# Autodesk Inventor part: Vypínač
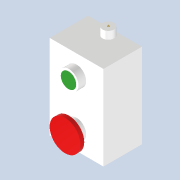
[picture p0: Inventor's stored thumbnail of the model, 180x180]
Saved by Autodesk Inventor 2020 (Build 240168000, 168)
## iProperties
Created: 2025-03
Part Number: Vypínač
Material: PC/ABS plast
Document SubType Name: Modeling
Designer: doma
Density: 0.357273 g/cm^3
Appearance: Hladká – bílá
Author: doma
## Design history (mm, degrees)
sketch "Náčrt1"
  geometry: L1 (-35, -55)-(35, -55); L2 (35, -55)-(35, 55); L3 (35, 55)-(-35, 55); L4 (-35, 55)-(-35, -55); L5 (-35, -55)-(35, 55); L6 (35, -55)-(-35, 55); 1 further point
  constraints: 12 end point, 2 midpoint, 2 parallel, 1 horizontal, 1 perpendicular
  dimensions: "d0" = 70 distance of L3.end L2.end; "d1" = 110 distance of L2.end L1.end
extrude "Vysunutí1" new body sketch "Náčrt1" distance "d2" = 50; taper "d3" = 0 deg
feature "Skořepina1" dims "d4" = 5
sketch "Náčrt2"
  geometry: C1 r 12.5 at (0, 30); C2 r 10 at (0, 30); 1 further point
  constraints: 2 centre point, 1 coincident
  dimensions: "d5" = 25 diameter of C1; "d6" = 20 diameter of C2; "d17" = 30 distance of C1.centre point (0, 0)
extrude "Vysunutí2" join sketch "Náčrt2" distance "d7" = 10; taper "d8" = 0 deg
extrude "Vysunutí3" join sketch "Náčrt2" distance "d9" = 10.5; taper "d10" = 0 deg
sketch "Náčrt3"
  geometry: C1 r 12.5 at (0, -30); 1 further point
  constraints: 1 centre point
  dimensions: "d11" = 25 diameter of C1; "d18" = 30 distance of C1.centre point (0, 0)
extrude "Vysunutí4" join sketch "Náčrt3" distance "d12" = 10; taper "d13" = 0 deg
sketch "Náčrt4"
  geometry: C1 r 12.5 at (0, 0) reference; C2 r 20 at (0, 0); 1 further point
  constraints: 1 centre point, 1 coincident
  dimensions: "d14" = 40 diameter of C2
extrude "Vysunutí5" join sketch "Náčrt4" distance "d15" = 5; taper "d16" = 0 deg
sketch "Náčrt5"
  geometry: C1 r 7.5 at (35, -8.75); 1 further point
  constraints: 1 centre point
  dimensions: "d19" = 15 diameter of C1; "d22" = 8.75 distance of point (35, 0) C1.centre
extrude "Vysunutí6" join sketch "Náčrt5" distance "d20" = 10; taper "d21" = 0 deg
node "Pracovní bod1"
node "Těleso1"
